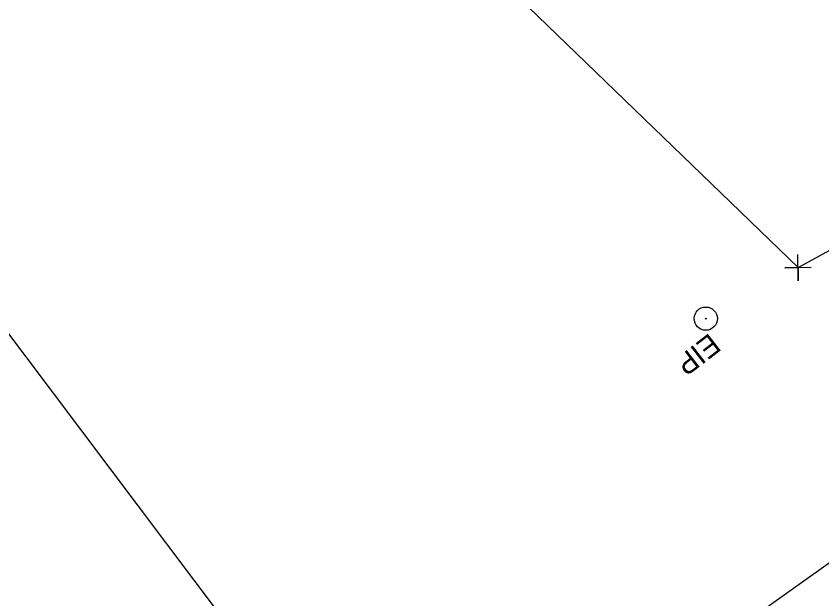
# Model space of a CAD drawing. Extents: x 1262092 to 1264624, y 774970 to 778314.
# Drawn here: x 1263407.7 to 1263560.4, y 776810.9 to 776921.4 of the extents above; entities that cross this region are included whole.
import ezdxf

# ---------------------------------------------------------------- set-up
doc = ezdxf.new("R2010")
doc.units = 0
for name, color, linetype in [('COGO Default Parcel', 7, 'Continuous'), ('Exist Property Corner CELL', 7, 'Continuous'), ('Exist Property Iron Pin CELL', 7, 'Continuous'), ('Exist Property Iron Pin Text', 7, 'Continuous'), ('Exist Property Line', 7, 'Continuous'), ('Exist Roads EOP', 7, 'Continuous')]:
    doc.layers.add(name, color=color, linetype=linetype)

# ---------------------------------------------------------------- blocks, each defined once
blk = doc.blocks.new('EXIST PROPERTY IRON PIN')
at = {"layer": 'Exist Property Iron Pin CELL'}
for radius in [0.0441, 0.00141]:
    blk.add_circle((0, 0), radius, dxfattribs=at)

msp = doc.modelspace()

# ---------------------------------------------------------------- linework, layer by layer
at = {"layer": 'COGO Default Parcel'}
for p, q in [((1262441.33, 778142.77), (1263481.78, 776760.76)), ((1263481.78, 776760.76), (1263626.7, 776863.98))]:
    msp.add_line(p, q, dxfattribs=at)
at = {"layer": 'Exist Property Corner CELL'}
msp.add_line((1263555.91, 776873.7), (1263555.91, 776873.7), dxfattribs=at)
msp.add_lwpolyline([(1263558.41, 776873.74), (1263553.41, 776873.66), (1263555.91, 776873.7), (1263555.96, 776871.2), (1263555.87, 776876.2)], dxfattribs=at)
at = {"layer": 'Exist Property Line'}
for p, q in [((1263389.96, 777034.11), (1263555.91, 776873.7)), ((1263555.9, 776873.69), (1263596.1, 776895.92))]:
    msp.add_line(p, q, dxfattribs=at)
at = {"layer": 'Exist Roads EOP'}
for points in [[(1263511, 776675.55), (1263536.41, 776690.7), (1263570.64, 776713.38), (1263606.79, 776738.89), (1263640.38, 776763.53), (1263671.49, 776785.83), (1263708, 776811.4), (1263736.42, 776831.66), (1263768.24, 776853.35), (1263805.25, 776879.67), (1263840.55, 776905.06), (1263875.28, 776930.44), (1263909.5, 776954.75), (1263950.37, 776982.41), (1263983.29, 777006.18), (1264027.54, 777035.52), (1264054.8, 777053.29), (1264082.17, 777072.95), (1264092.76, 777080.37)], [(1263532.95, 776644.88), (1263556.37, 776661.77), (1263588.74, 776685.14), (1263625.33, 776711.31), (1263659.49, 776736.27), (1263691.33, 776758.54), (1263726.37, 776783.82), (1263756.25, 776805.33), (1263773.74, 776816.65), (1263781.38, 776820.01)]]:
    msp.add_spline(points, degree=3, dxfattribs=at)

# ---------------------------------------------------------------- block references
at = {"layer": 'Exist Property Iron Pin CELL', "xscale": 50, "yscale": 50}
msp.add_blockref('EXIST PROPERTY IRON PIN', (1263538.41, 776864.02), dxfattribs=at)

# ---------------------------------------------------------------- texts
at = {"layer": 'Exist Property Iron Pin Text'}
msp.add_text('EIP', height=4, rotation=217.7197, dxfattribs=at).set_placement((1263539.15, 776861.42))

doc.saveas('drawing.dxf')
